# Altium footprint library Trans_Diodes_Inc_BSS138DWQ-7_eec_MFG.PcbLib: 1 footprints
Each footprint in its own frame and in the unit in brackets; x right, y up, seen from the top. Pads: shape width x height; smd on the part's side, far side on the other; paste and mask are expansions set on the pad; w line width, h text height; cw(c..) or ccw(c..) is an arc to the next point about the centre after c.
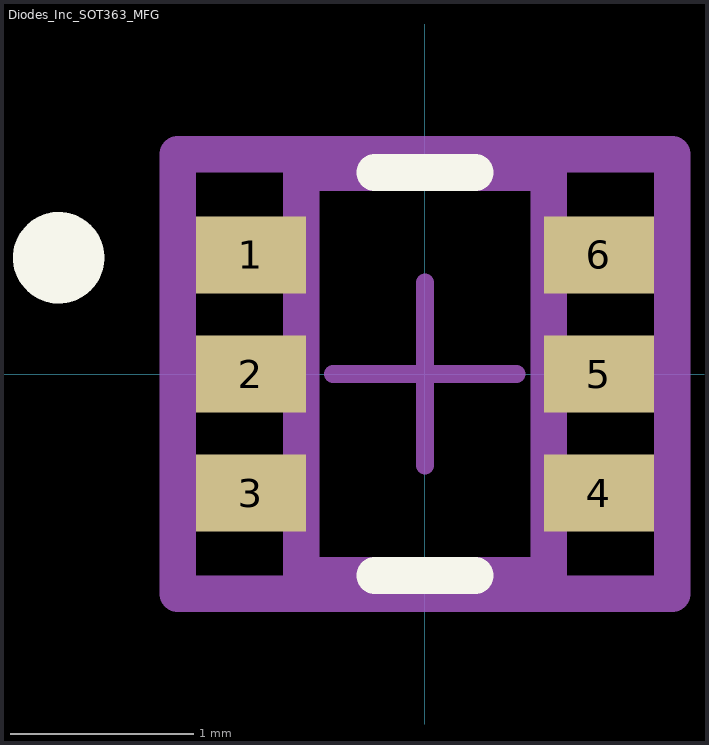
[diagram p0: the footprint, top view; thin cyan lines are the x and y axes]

## Diodes_Inc_SOT363_MFG [mm]
pads (6):
  rect 0.6x0.42 smd paste+0 mask+0: 1(-0.95,0.65) 2(-0.95,0) 3(-0.95,-0.65) 4(0.95,-0.65) 5(0.95,0) 6(0.95,0.65)
Top Overlay:
  circle w0.25: c-2,0.635 r0.125
  lines w0.2: -0.275,-1.1 0.275,-1.1 ; -0.275,1.1 0.275,1.1
Mechanical 10:
  lines w0.2: -1.35,-1.2 1.35,-1.2 1.35,1.2 -1.35,1.2 -1.35,-1.2
  text ".Designator" at 0,0.188 h1
Mechanical 12:
  lines w0.2: -0.675,-1.1 0.675,-1.1 0.675,1.1 -0.675,1.1 -0.675,-1.1
Mechanical 15:
  lines w0.1: -0.5,0 0.5,0 ; 0,-0.5 0,0.5
  lines w0.2: -1.35,-1.2 1.35,-1.2 1.35,1.2 -1.35,1.2 -1.35,-1.2
3D body "Trans_Diodes_Inc_BSS138DWQ-7_eec.STEP": height 0.25, standoff 0, extent -1.35,-1.2 1.35,1.2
